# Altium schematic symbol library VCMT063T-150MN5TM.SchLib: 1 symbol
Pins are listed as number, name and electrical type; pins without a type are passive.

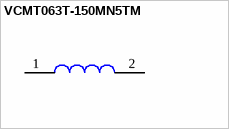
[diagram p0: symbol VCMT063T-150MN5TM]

## VCMT063T-150MN5TM
designator L?
Manufacturer: Cyntec; CompType: Inductor; Value: 15uH
footprint VCMT063T-150MN5TM
pins: 1, 2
